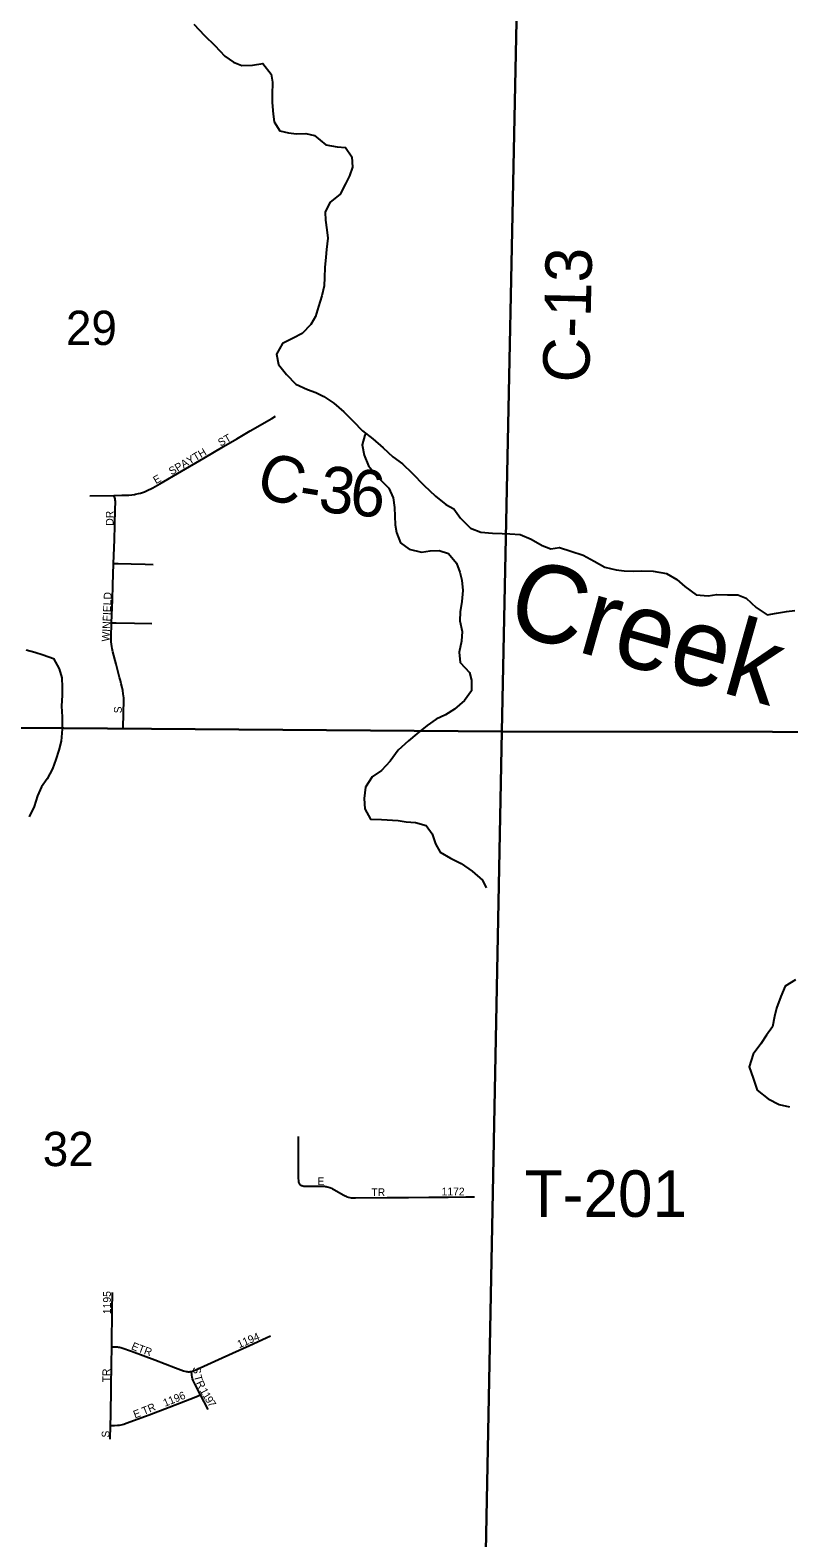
# Model space of a CAD drawing. Extents: x 1772825 to 1773716, y 1138558 to 1139032.
# Drawn here: x 1772828.724 to 1772829.187, y 1138561.147 to 1138562.068 of the extents above; entities that cross this region are included whole.
import ezdxf

# ---------------------------------------------------------------- set-up
doc = ezdxf.new("R2010")
doc.units = 0
for name, color, linetype in [('GM_X_County_Road_Text', 7, 'Continuous'), ('GM_X_Minor_River', 7, 'Continuous'), ('GM_X_Minor_River_Text', 7, 'Continuous'), ('GM_X_Section', 7, 'Continuous'), ('GM_X_Section_Text', 7, 'Continuous'), ('GM_X_Township_Road_Text', 7, 'Continuous'), ('GM_X_Township_Subdivision', 7, 'Continuous'), ('GM_X_Township_Subdivision_Text', 7, 'Continuous')]:
    doc.layers.add(name, color=color, linetype=linetype)

msp = doc.modelspace()

# ---------------------------------------------------------------- linework, layer by layer
at = {"layer": 'GM_X_Minor_River'}
for points in [[(1772828.82361, 1138562.07185), (1772828.83001, 1138562.06497), (1772828.83641, 1138562.05885), (1772828.84244, 1138562.05235), (1772828.84791, 1138562.04852), (1772828.85283, 1138562.04658), (1772828.85947, 1138562.04672), (1772828.86574, 1138562.04781), (1772828.87082, 1138562.04132), (1772828.87173, 1138562.03638), (1772828.87149, 1138562.02861), (1772828.87145, 1138562.02386), (1772828.87197, 1138562.01684), (1772828.87269, 1138562.01209), (1772828.87607, 1138562.00675), (1772828.88137, 1138562.00538), (1772828.8863, 1138562.00478), (1772828.892, 1138562.00511), (1772828.8973, 1138562.00375), (1772828.90428, 1138561.998), (1772828.9111, 1138561.99681), (1772828.91622, 1138561.99639), (1772828.92016, 1138561.99086), (1772828.9205, 1138561.98441), (1772828.91875, 1138561.97911), (1772828.91625, 1138561.97419), (1772828.91298, 1138561.96795), (1772828.90668, 1138561.96288), (1772828.90379, 1138561.95702), (1772828.90413, 1138561.95208), (1772828.90485, 1138561.9462), (1772828.90557, 1138561.94107), (1772828.90476, 1138561.93424), (1772828.90435, 1138561.9295), (1772828.90373, 1138561.92325), (1772828.9035, 1138561.91699), (1772828.90327, 1138561.91186), (1772828.90171, 1138561.9058), (1772828.89977, 1138561.89937), (1772828.89802, 1138561.89331), (1772828.89513, 1138561.8884), (1772828.88978, 1138561.88275), (1772828.88426, 1138561.87994), (1772828.87778, 1138561.87676), (1772828.87413, 1138561.87015), (1772828.87541, 1138561.86388), (1772828.8803, 1138561.85777), (1772828.88595, 1138561.85185), (1772828.89314, 1138561.84857), (1772828.89806, 1138561.84682), (1772828.90297, 1138561.84432), (1772828.9092, 1138561.84029), (1772828.91524, 1138561.83493), (1772828.92089, 1138561.82919), (1772828.92673, 1138561.82346), (1772828.93295, 1138561.81848), (1772828.93936, 1138561.81293), (1772828.94521, 1138561.80757), (1772828.95106, 1138561.80316), (1772828.95708, 1138561.79742), (1772828.96424, 1138561.79016), (1772828.97121, 1138561.78347), (1772828.97763, 1138561.77829), (1772828.98254, 1138561.77579), (1772828.98648, 1138561.77007), (1772828.9927, 1138561.76395), (1772828.99894, 1138561.76144), (1772829.00615, 1138561.76081), (1772829.01203, 1138561.76058)], [(1772828.92873, 1138561.82185), (1772828.92804, 1138561.82079), (1772828.92647, 1138561.81473), (1772828.92776, 1138561.80846), (1772828.93037, 1138561.80199), (1772828.93638, 1138561.79473), (1772828.94279, 1138561.78842), (1772828.9454, 1138561.78252), (1772828.94631, 1138561.77644), (1772828.94646, 1138561.77113), (1772828.94661, 1138561.76601), (1772828.94752, 1138561.76126), (1772828.94995, 1138561.75498), (1772828.95523, 1138561.75114), (1772828.96262, 1138561.74919), (1772828.96794, 1138561.7501), (1772828.97344, 1138561.75024), (1772828.97931, 1138561.74849), (1772828.9842, 1138561.74257), (1772828.98606, 1138561.73706), (1772828.98735, 1138561.73212), (1772828.98806, 1138561.72585), (1772828.98744, 1138561.71902), (1772828.98645, 1138561.71277), (1772828.98622, 1138561.70727), (1772828.9875, 1138561.70081), (1772828.98708, 1138561.69493), (1772828.9857, 1138561.68811), (1772828.98641, 1138561.68184), (1772828.99206, 1138561.67573), (1772828.99335, 1138561.67097), (1772828.99331, 1138561.66452), (1772828.9889, 1138561.65867), (1772828.98279, 1138561.65322), (1772828.97745, 1138561.64984), (1772828.97174, 1138561.64723), (1772828.96621, 1138561.64329), (1772828.95991, 1138561.63821), (1772828.95476, 1138561.63389), (1772828.94846, 1138561.62824), (1772828.94347, 1138561.62164), (1772828.93831, 1138561.61579), (1772828.93259, 1138561.61204), (1772828.92856, 1138561.60562), (1772828.92775, 1138561.5988), (1772828.92808, 1138561.59234), (1772828.93164, 1138561.58606), (1772828.93828, 1138561.58582), (1772828.94852, 1138561.58536), (1772828.95326, 1138561.58456), (1772828.95914, 1138561.58414), (1772828.96558, 1138561.58219), (1772828.96914, 1138561.57723), (1772828.97119, 1138561.57096), (1772828.97419, 1138561.566), (1772828.98042, 1138561.56235), (1772828.98704, 1138561.55907), (1772828.99364, 1138561.55428), (1772829.00006, 1138561.54892), (1772829.0023, 1138561.54416)], [(1772829.01203, 1138561.76058), (1772829.01677, 1138561.76035), (1772829.02303, 1138561.76012), (1772829.02965, 1138561.75722), (1772829.03645, 1138561.75338), (1772829.04175, 1138561.75125), (1772829.04707, 1138561.75216), (1772829.05407, 1138561.74983), (1772829.06146, 1138561.74749), (1772829.06826, 1138561.74365), (1772829.07468, 1138561.74), (1772829.08169, 1138561.73843), (1772829.08662, 1138561.73782), (1772829.09212, 1138561.73759), (1772829.09724, 1138561.73774), (1772829.10426, 1138561.73769), (1772829.11241, 1138561.7363), (1772829.11884, 1138561.73245), (1772829.12374, 1138561.72824), (1772829.13053, 1138561.72326), (1772829.13793, 1138561.72263), (1772829.14325, 1138561.72335), (1772829.14969, 1138561.72311), (1772829.15596, 1138561.72326), (1772829.16106, 1138561.72113), (1772829.16728, 1138561.71539), (1772829.17408, 1138561.71098), (1772829.17978, 1138561.71188), (1772829.18586, 1138561.71297), (1772829.1908, 1138561.71351)], [(1772828.72103, 1138561.68953), (1772828.72633, 1138561.68816), (1772828.73144, 1138561.68661), (1772828.73788, 1138561.68428), (1772828.74125, 1138561.678), (1772828.74292, 1138561.67248), (1772828.74306, 1138561.66679), (1772828.74303, 1138561.66185), (1772828.74279, 1138561.65522), (1772828.74312, 1138561.64857), (1772828.74307, 1138561.64117), (1772828.74244, 1138561.63378), (1772828.74108, 1138561.62829), (1772828.73933, 1138561.62261), (1772828.7372, 1138561.61693), (1772828.73393, 1138561.61069), (1772828.73048, 1138561.60579), (1772828.72797, 1138561.6003), (1772828.72603, 1138561.59387), (1772828.72294, 1138561.58744)], [(1772829.19124, 1138561.4879), (1772829.18495, 1138561.48416), (1772829.18244, 1138561.47772), (1772829.17973, 1138561.47072), (1772829.17856, 1138561.46561), (1772829.17718, 1138561.45917), (1772829.17354, 1138561.45407), (1772829.17009, 1138561.44879), (1772829.16549, 1138561.44256), (1772829.16296, 1138561.4348), (1772829.16538, 1138561.42795), (1772829.16779, 1138561.42053), (1772829.17459, 1138561.41517), (1772829.18139, 1138561.41189), (1772829.18764, 1138561.41033)]]:
    msp.add_lwpolyline(points, dxfattribs=at)
at = {"layer": 'GM_X_Section'}
for points in [[(1772829.02215, 1138562.14292), (1772829.0119, 1138561.63975), (1772828.50281, 1138561.64361), (1772828.50962, 1138562.14244)], [(1772829.51894, 1138562.14124), (1772829.50793, 1138561.63902), (1772829.0119, 1138561.63975), (1772829.02215, 1138562.14292)], [(1772828.50281, 1138561.64361), (1772829.0119, 1138561.63975), (1772829.00204, 1138561.13886), (1772828.99654, 1138561.1389), (1772828.49974, 1138561.13793), (1772828.49728, 1138561.13776)], [(1772829.50793, 1138561.63902), (1772829.49844, 1138561.13775), (1772829.00204, 1138561.13886), (1772829.0119, 1138561.63975)]]:
    msp.add_lwpolyline(points, close=True, dxfattribs=at)
at = {"layer": 'GM_X_Township_Subdivision'}
for points in [[(1772828.78783, 1138561.78463), (1772828.78978, 1138561.78502), (1772828.79088, 1138561.78532), (1772828.79212, 1138561.7857), (1772828.7934, 1138561.78619), (1772828.79467, 1138561.78674), (1772828.79855, 1138561.78863), (1772828.80289, 1138561.791), (1772828.81605, 1138561.79864), (1772828.82971, 1138561.80666), (1772828.84176, 1138561.81375), (1772828.84979, 1138561.81847), (1772828.85809, 1138561.82334), (1772828.87124, 1138561.83099), (1772828.8735, 1138561.83231)], [(1772828.76005, 1138561.78375), (1772828.77471, 1138561.78394)], [(1772828.77457, 1138561.7424), (1772828.77502, 1138561.75671), (1772828.77527, 1138561.76572), (1772828.77559, 1138561.77575), (1772828.77572, 1138561.77965), (1772828.77567, 1138561.7804), (1772828.77559, 1138561.78105), (1772828.77547, 1138561.78175), (1772828.77526, 1138561.78241), (1772828.77471, 1138561.78394)], [(1772828.77471, 1138561.78394), (1772828.77963, 1138561.78401), (1772828.7839, 1138561.78413), (1772828.7857, 1138561.78429), (1772828.78738, 1138561.78454), (1772828.78783, 1138561.78463)], [(1772828.77329, 1138561.70612), (1772828.7738, 1138561.72007), (1772828.77413, 1138561.72904), (1772828.77457, 1138561.7424)], [(1772828.77457, 1138561.7424), (1772828.77739, 1138561.7423), (1772828.78537, 1138561.74201), (1772828.79388, 1138561.74181), (1772828.79877, 1138561.74173)], [(1772828.78036, 1138561.64084), (1772828.78069, 1138561.65177), (1772828.78078, 1138561.658), (1772828.78072, 1138561.66021), (1772828.78064, 1138561.6614), (1772828.78047, 1138561.66263), (1772828.7801, 1138561.66464), (1772828.77969, 1138561.66662), (1772828.77916, 1138561.66888), (1772828.77871, 1138561.67081), (1772828.77821, 1138561.67276), (1772828.77605, 1138561.68088), (1772828.77407, 1138561.68837), (1772828.77364, 1138561.69034), (1772828.7734, 1138561.69168), (1772828.77323, 1138561.69306), (1772828.77312, 1138561.69442), (1772828.77302, 1138561.69589), (1772828.77304, 1138561.69719), (1772828.77329, 1138561.70612)], [(1772828.77329, 1138561.70612), (1772828.77608, 1138561.70605), (1772828.78739, 1138561.70576), (1772828.79783, 1138561.70556)], [(1772828.88727, 1138561.39223), (1772828.88744, 1138561.37956), (1772828.88743, 1138561.36664), (1772828.88745, 1138561.36546), (1772828.88751, 1138561.36484), (1772828.88761, 1138561.36431), (1772828.88776, 1138561.36386), (1772828.88798, 1138561.36344), (1772828.88819, 1138561.36316), (1772828.88855, 1138561.36279), (1772828.88893, 1138561.36254), (1772828.88929, 1138561.36237), (1772828.88965, 1138561.36221), (1772828.89028, 1138561.362), (1772828.89085, 1138561.3619), (1772828.89147, 1138561.36184), (1772828.89513, 1138561.3618), (1772828.90252, 1138561.36185), (1772828.90349, 1138561.3618), (1772828.90396, 1138561.36176), (1772828.90438, 1138561.36172), (1772828.90511, 1138561.36158), (1772828.90587, 1138561.36137), (1772828.9067, 1138561.36111), (1772828.90763, 1138561.36073), (1772828.90838, 1138561.36034), (1772828.90954, 1138561.3597), (1772828.91483, 1138561.35656), (1772828.91644, 1138561.35578), (1772828.91713, 1138561.35545), (1772828.91791, 1138561.35517), (1772828.91882, 1138561.35492), (1772828.91972, 1138561.3548), (1772828.92108, 1138561.35471), (1772828.92231, 1138561.35471), (1772828.94171, 1138561.35492), (1772828.95477, 1138561.35498), (1772828.9672, 1138561.35509), (1772828.97904, 1138561.35522), (1772828.98987, 1138561.35535), (1772828.99518, 1138561.35535)], [(1772828.77341, 1138561.26376), (1772828.77343, 1138561.26497), (1772828.77365, 1138561.2861), (1772828.77377, 1138561.29696)], [(1772828.82217, 1138561.24872), (1772828.82287, 1138561.24893), (1772828.82365, 1138561.24922), (1772828.82478, 1138561.24968), (1772828.82974, 1138561.2519), (1772828.84084, 1138561.257), (1772828.85761, 1138561.26457), (1772828.86773, 1138561.26918), (1772828.87053, 1138561.27045)], [(1772828.7727, 1138561.21571), (1772828.77279, 1138561.22204), (1772828.77305, 1138561.23882), (1772828.77321, 1138561.25317), (1772828.77341, 1138561.26376)], [(1772828.77341, 1138561.26376), (1772828.77521, 1138561.26376), (1772828.7762, 1138561.26376), (1772828.77692, 1138561.26371), (1772828.77757, 1138561.26363), (1772828.77823, 1138561.2635), (1772828.77888, 1138561.26334), (1772828.77959, 1138561.26313), (1772828.78539, 1138561.26108), (1772828.79978, 1138561.2557), (1772828.81227, 1138561.251), (1772828.81724, 1138561.24915), (1772828.81799, 1138561.24892), (1772828.81879, 1138561.24871), (1772828.81945, 1138561.24861), (1772828.82009, 1138561.24855), (1772828.82078, 1138561.24855), (1772828.82141, 1138561.24861), (1772828.82217, 1138561.24872)], [(1772828.82755, 1138561.23433), (1772828.8243, 1138561.24065), (1772828.82322, 1138561.24321), (1772828.82283, 1138561.24424), (1772828.82259, 1138561.24528), (1772828.82242, 1138561.24647), (1772828.82217, 1138561.24872)], [(1772828.7727, 1138561.21571), (1772828.77514, 1138561.21571), (1772828.77699, 1138561.21579), (1772828.77815, 1138561.21591), (1772828.77912, 1138561.21609), (1772828.78073, 1138561.21653), (1772828.7823, 1138561.21707), (1772828.79618, 1138561.22221), (1772828.80841, 1138561.2269), (1772828.82473, 1138561.23324), (1772828.82755, 1138561.23433)], [(1772828.83229, 1138561.22537), (1772828.82755, 1138561.23433)], [(1772828.77252, 1138561.20736), (1772828.7727, 1138561.21571)]]:
    msp.add_lwpolyline(points, dxfattribs=at)

# ---------------------------------------------------------------- texts
at = {"layer": 'GM_X_County_Road_Text'}
for s, height, rotation, p in [('C-13', 0.028409, 88.66081, (1772829.06518, 1138561.85263)), ('C', 0.02841, 342.55122, (1772828.86014, 1138561.78451)), ('3', 0.02841, 351.96822, (1772828.89889, 1138561.77452)), ('6', 0.02841, 356.22109, (1772828.91851, 1138561.77184)), ('-', 0.02841, 350.7562, (1772828.88672, 1138561.77649))]:
    msp.add_text(s, height=height, rotation=rotation, dxfattribs=at).set_placement(p)
at = {"layer": 'GM_X_Minor_River_Text'}
msp.add_text('Creek', height=0.047369, rotation=344.22331, dxfattribs=at).set_placement((1772829.01304, 1138561.70115))
at = {"layer": 'GM_X_Section_Text'}
for s, p in [('29', (1772828.74542, 1138561.87582)), ('32', (1772828.73125, 1138561.37415))]:
    msp.add_text(s, height=0.020928, rotation=0.00001, dxfattribs=at).set_placement(p)
at = {"layer": 'GM_X_Township_Road_Text'}
msp.add_text('T-201', height=0.028409, rotation=0.00001, dxfattribs=at).set_placement((1772829.02583, 1138561.34315))
at = {"layer": 'GM_X_Township_Subdivision_Text'}
for s, height, rotation, p in [('ST', 0.004735, 29.7432, (1772828.83997, 1138561.81365)), ('SPAYTH', 0.004735, 30.50754, (1772828.80999, 1138561.79615)), ('E', 0.00473, 29.73143, (1772828.80039, 1138561.79073)), ('DR', 0.004735, 90, (1772828.77453, 1138561.76537)), ('WINFIELD', 0.004735, 87.47463, (1772828.77203, 1138561.69456)), ('S', 0.00473, 90, (1772828.77953, 1138561.65079)), ('E', 0.00473, 0.00001, (1772828.89917, 1138561.36251)), ('TR', 0.004735, 0.00001, (1772828.93208, 1138561.35584)), ('1172', 0.004735, 0.00001, (1772828.975, 1138561.35626)), ('1195', 0.004735, 90, (1772828.77286, 1138561.28371)), ('E', 0.00473, 336.81272, (1772828.78493, 1138561.26244)), ('1194', 0.004735, 22.93374, (1772828.85131, 1138561.26285)), ('TR', 0.004735, 340.56804, (1772828.78904, 1138561.26079)), ('TR', 0.004735, 90, (1772828.77244, 1138561.24204)), ('S', 0.00473, 275.41703, (1772828.82297, 1138561.25128)), ('T', 0.00473, 284.79952, (1772828.82358, 1138561.24589)), ('R', 0.00473, 295.49816, (1772828.82476, 1138561.24176)), ('1', 0.00473, 297.67942, (1772828.82703, 1138561.23709)), ('TR', 0.004735, 22.93429, (1772828.79299, 1138561.22202)), ('1196', 0.004735, 22.16248, (1772828.80593, 1138561.22703)), ('1', 0.00473, 301.43525, (1772828.82855, 1138561.23421)), ('9', 0.00473, 302.2141, (1772828.83011, 1138561.23166)), ('7', 0.00473, 302.27299, (1772828.83167, 1138561.22919)), ('E', 0.00473, 20.56203, (1772828.7876, 1138561.21995)), ('S', 0.00473, 90, (1772828.77202, 1138561.20829))]:
    msp.add_text(s, height=height, rotation=rotation, dxfattribs=at).set_placement(p)

doc.saveas('drawing.dxf')
